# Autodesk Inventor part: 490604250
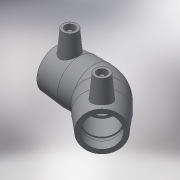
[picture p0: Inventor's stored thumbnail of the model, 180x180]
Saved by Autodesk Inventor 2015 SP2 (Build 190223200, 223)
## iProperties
Created: 2017-06
Part Number: 490604250
Material: Generic
Description: PLASSON 45° ELBOW 250
Document SubType Name: Modeling
Designer: KIM
Mass: 55.0731 g
Surface Area: 148.067 cm^2
Volume: 55.0731 cm^3
Density: 1 g/cm^3
Appearance: Default
Author: KIM
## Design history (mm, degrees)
derived "490604.ipt"
feature "Solid1::490604.ipt"
tag "TaggingFeature1"
body "Solid1"
other parameters: "d2" = 326, "d4" = 142.75, "d5" = 293.4, "d8" = 168 deg, "d10" = 51.6, "d11" = 17.2, "d14" = 17.6296, "d19" = 3.52592, "d20" = 168 deg, "d22" = 299.92, "d23" = 326, "d24" = 290.9224, "d29" = 151, "d30" = 15, "d31" = 199.85, "d34" = 5 deg, "d35" = 12, "d39" = 0, "d41" = 4, "d42" = 14, "d43" = 0, "d44" = 9.6, "d45" = 4.8, "d46" = 6, "d47" = 0, "d50" = 212.5, "d51" = 51.6, "d52" = 129, "d54" = 135 deg, "d67" = 45 deg, "d71" = 135 deg, "d75" = 16.3, "d82" = 45 deg, "d83" = 129, "d84" = 293.4, "d86" = 146.7, "d87" = 135 deg, "d88" = 571, "d90" = 129, "d91" = 0, "d92" = 129, "d93" = 0, "d94" = 135 deg, "d95" = 149.96, "d98" = 571, "d99" = 194.14, "d101" = 3, "d102" = 0, "d103" = 3, "d104" = 0, "d105" = 37.41, "d106" = 9.3525, "L_" = 571, "L_1" = 129, "D_" = 326, "A_" = 151, "d_2" = 12
